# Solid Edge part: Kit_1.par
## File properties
Sűrűség: 0,000 kg/m^3
Pontosság: 0,990
Author: bmolnar
Last saved by: ahadarics
Revision: 76
Username: bmolnar
Dokumentum tartalom típus: 0
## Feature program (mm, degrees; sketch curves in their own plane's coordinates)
base feature "unnamed BaseFeature 1"
sketch for "Furat_1" plane through (-47.6845, 0, -79.5) normal (-0.999962, 0, -0.008727) x-axis (0, -1, 0)
hole "Furat_1" diameter 8.566 finite
sketch for "Furat_2" plane through (0, 0, -87) normal (0, 0, -1) x-axis (0, -1, 0)
  hole centre (-36, 36) bore radius 4.188
hole "Furat_2" nominal diameter 10 through
sketch for "unnamed Hole 1" plane through (0, 0, -87) normal (0, 0, -1) x-axis (0, -1, 0)
  hole centre (36, 36) bore radius 4.188
hole "unnamed Hole 1" through
sketch for "unnamed Hole 2" plane through (0, 0, -87) normal (0, 0, -1) x-axis (0, -1, 0)
  hole centre (36, -36) bore radius 4.188
hole "unnamed Hole 2" through
sketch for "unnamed Hole 3" plane through (0, 0, -87) normal (0, 0, -1) x-axis (0, -1, 0)
  hole centre (-36, -36) bore radius 4.188
hole "unnamed Hole 3" through
pattern "unnamed Pattern 1" of "Furat_2", "unnamed Hole 1", "unnamed Hole 2", "unnamed Hole 3"
thread "unnamed Thread 1"
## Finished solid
Body 1: solid body, 307 faces, 742 edges, 452 vertices.
  Faces by surface: plane 139, cylinder 73, swept 60, cone 24, torus 10, spline 1
  Edges by curve: line 421, circle 152, spline 120, ellipse 32, curve on surface 17
Bounding box of the edges (mm; curved faces can reach further): 95.500 x 95.500 x 15.000, from (-47.75, -47.75, -87) to (47.75, 47.75, -72).
Cylindrical faces by radius (mm): R0.2 x48, R0.2017 x2, R0.2018 x2, R4.188 x4, R4.283 x1, R4.9 x4, R5.15 x4, R6.75 x4, R10.3 x1, R10.95 x1, R11.5 x1, R12.5 x1
Conical faces (half-angle, radius in mm at the cone's reference point): 0.5 deg R10 x4, 0.5 deg R13.5 x2, 7 deg R11.7695 x1, 14 deg R10.15 x1, 14 deg R10.557 x1, 17 deg R10.15 x1, 23 deg R10.9211 x1, 42.5 deg R10.137 x1, 45 deg R4.185 x4, 45 deg R4.985 x4, 45 deg R11.1 x1, 84 deg R10.512 x1, 85 deg R12.1625 x1, 87 deg R10.2157 x1
Toroidal faces (ring radius, tube radius in mm): R4.7 r0.2 x8, R10.9008 r0.225 x1, R11.3914 r0.325 x1
Planar faces by outward normal: +x 14, +y 14, +z 1, -x 16, -y 13, -z 19, oblique 62
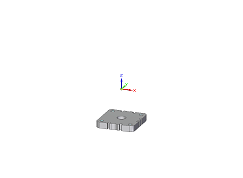
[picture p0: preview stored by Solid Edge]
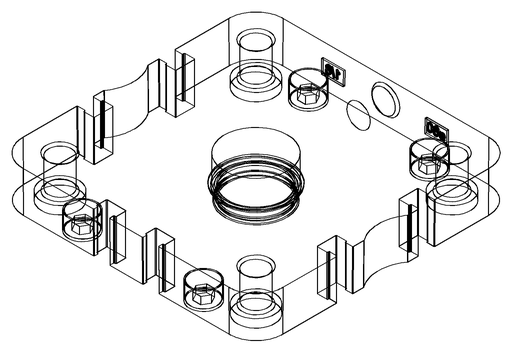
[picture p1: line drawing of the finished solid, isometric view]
